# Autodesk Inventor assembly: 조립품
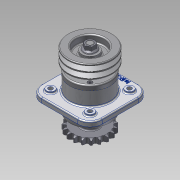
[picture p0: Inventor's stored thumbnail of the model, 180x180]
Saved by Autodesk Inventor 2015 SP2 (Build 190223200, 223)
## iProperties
Created: 2015-07
Part Number: 조립품
Document SubType Name: Assembly
Designer: AMC
Author: AMC
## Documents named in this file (12)
- C:\Users\AMC\Desktop\450735V1013\조립품.iam
- C:\Users\AMC\Desktop\450735V1013\본체.ipt
- C:\Users\AMC\Desktop\450735V1013\2-커버.ipt
- C:\Users\AMC\Desktop\450735V1013\3-축.ipt
- C:\Users\AMC\Desktop\450735V1013\4-V벨트풀리.ipt
- C:\Users\AMC\Desktop\450735V1013\5-체인 스프로킷.ipt
- C:\Users\AMC\Desktop\450735V1013\6-베어링 6206.ipt
- C:\Users\AMC\Desktop\450735V1013\7-부시.ipt
- C:\Users\AMC\Desktop\450735V1013\8-오일실 30x42.ipt
- C:\Users\AMC\Desktop\450735V1013\9-M16-너트.ipt
- C:\Users\AMC\Desktop\450735V1013\10-M6.ipt
- C:\Users\AMC\Desktop\450735V1013\11-키 6x6.ipt
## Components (22 placed, 10 different names)
1. 2-커버:1
2. 3-축:1
3. 4-V벨트풀리:1 — 각도:1
4. 5-체인 스프로킷:1 — 각도:2
5. 6-베어링 6206:1
6. 7-부시:1
7. 8-8-오일실 30x42:1
8. 9-M16 너트:1
9. 11-키 6x6:1 — 각도:1
10. 6-베어링 6206:2
11. 2-커버:2
12. 8-8-오일실 30x42:2
13. 9-M16 너트:2
14. 11-키 6x6:2 — 각도:2
15. 10-M6:1
16. 10-M6:3
17. 10-M6:4
18. 10-M6:5
19. 10-M6:2
20. 10-M6:6
21. 10-M6:7
22. 10-M6:8
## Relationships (2: Angle 2)
- 각도:1 [Angle]: 4-V벨트풀리:1 ↔ 11-키 6x6:1
- 각도:2 [Angle]: 5-체인 스프로킷:1 ↔ 11-키 6x6:2
